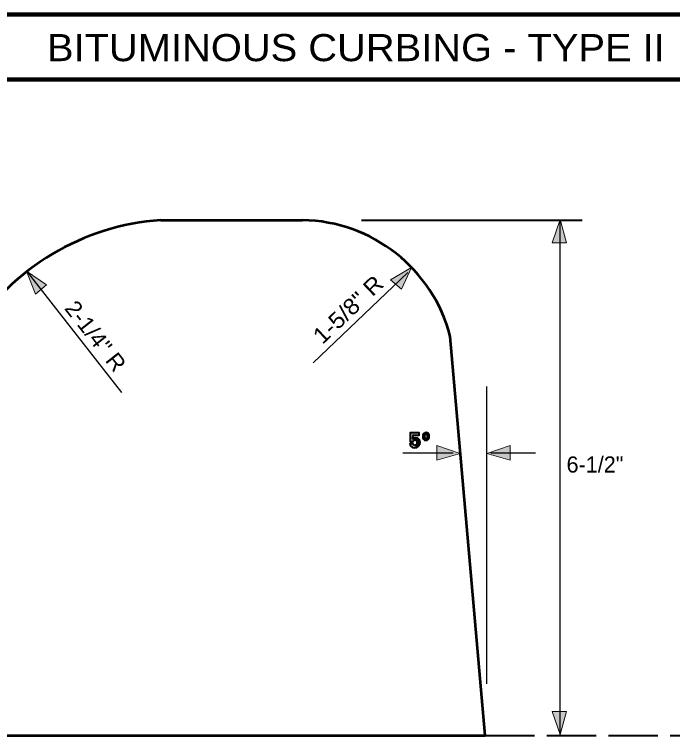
# Model space of a CAD drawing. Extents: x -9575 to -7980, y -62851 to -56618.
# Drawn here: x -9090 to -8521, y -62411 to -61789 of the extents above; entities that cross this region are included whole.
import ezdxf
from ezdxf.enums import TextEntityAlignment as Align

# ---------------------------------------------------------------- set-up
doc = ezdxf.new("R2010")
doc.units = 0
doc.header["$LTSCALE"] = 7.1
doc.linetypes.add('LONG_DASHED', pattern=[7.5, 6, -1.5])
doc.layers.add('1', color=7, linetype='Continuous', lineweight=13)
doc.layers.add('3', color=7, linetype='Continuous', lineweight=40)

msp = doc.modelspace()

# ---------------------------------------------------------------- hatches: boundary and pattern name
at = {"layer": '1'}
for points in [[(-8618.4, -61965.96), (-8625.3, -61985.96), (-8612.8, -61985.96)], [(-8746.68, -62007.2), (-8764.86, -62018), (-8755.32, -62026.08)], [(-9079.16, -62010.58), (-9071.52, -62030.32), (-9061.98, -62022.24)], [(-8704.8, -62167.92), (-8724.8, -62161.02), (-8724.8, -62173.52)], [(-8681.7, -62167.92), (-8661.7, -62161.02), (-8661.7, -62173.52)], [(-8618.4, -62410.64), (-8625.3, -62390.64), (-8612.8, -62390.64)]]:
    msp.add_hatch(color=256, dxfattribs=at).paths.add_polyline_path(points)
at = {"layer": '3'}
for points in [[(-8748.06, -62156.84), (-8748.08, -62157.5), (-8745.4, -62157.5), (-8745.06, -62156.84), (-8745.06, -62156.84), (-8745.06, -62156.84), (-8745.06, -62156.84), (-8744.52, -62156.38), (-8744.4, -62156.36), (-8743.86, -62156.2), (-8739.98, -62156.2), (-8740.38, -62155.52), (-8740.86, -62155.2), (-8745.58, -62155.2), (-8745.54, -62154.64), (-8745.54, -62154.6), (-8745.38, -62152.08), (-8740.18, -62152.08), (-8740.18, -62150.04), (-8747.8, -62150.04), (-8747.88, -62152.08), (-8747.98, -62154.6), (-8747.98, -62154.64), (-8748, -62155.2), (-8748.02, -62155.52), (-8748.04, -62156.2), (-8748.04, -62156.36), (-8748.04, -62156.38), (-8748.06, -62156.84), (-8748.06, -62156.84)], [(-8736.98, -62154.38), (-8736.98, -62154.52), (-8735.1, -62154.52), (-8735.14, -62154.38), (-8735.26, -62153.96), (-8735.28, -62153.88), (-8735.34, -62153.18), (-8735.34, -62153.16), (-8735.34, -62153.08), (-8735.32, -62153.02), (-8735.26, -62152.36), (-8735.24, -62152.24), (-8735.1, -62151.82), (-8735.06, -62151.66), (-8735.04, -62151.64), (-8735.04, -62151.64), (-8735.02, -62151.6), (-8734.7, -62151.26), (-8734.62, -62151.24), (-8734.26, -62151.14), (-8731.88, -62151.14), (-8732.14, -62150.68), (-8732.2, -62150.58), (-8733.12, -62150), (-8733.18, -62149.98), (-8734.26, -62149.82), (-8735.22, -62149.98), (-8735.42, -62150), (-8736.26, -62150.58), (-8736.38, -62150.68), (-8736.62, -62151.14), (-8736.66, -62151.24), (-8736.68, -62151.26), (-8736.86, -62151.6), (-8736.88, -62151.64), (-8736.9, -62151.66), (-8736.98, -62151.82), (-8737.02, -62152.24), (-8737.04, -62152.36), (-8737.12, -62153.02), (-8737.14, -62153.08), (-8737.14, -62153.16), (-8737.14, -62153.18), (-8737.06, -62153.88), (-8737.04, -62153.96)], [(-8733.92, -62155.06), (-8734.24, -62155.16), (-8731.94, -62155.16), (-8731.88, -62155.06), (-8731.86, -62155), (-8731.68, -62154.64), (-8731.66, -62154.56), (-8731.62, -62154.52), (-8731.56, -62154.38), (-8731.52, -62153.96), (-8731.5, -62153.88), (-8731.42, -62153.18), (-8731.42, -62153.16), (-8731.4, -62153.08), (-8731.4, -62153.02), (-8731.5, -62152.36), (-8731.52, -62152.24), (-8731.58, -62151.82), (-8731.6, -62151.66), (-8731.6, -62151.64), (-8731.62, -62151.6), (-8731.62, -62151.6), (-8731.82, -62151.26), (-8731.82, -62151.26), (-8731.84, -62151.24), (-8731.88, -62151.14), (-8734.26, -62151.14), (-8733.86, -62151.24), (-8733.84, -62151.26), (-8733.5, -62151.6), (-8733.5, -62151.64), (-8733.48, -62151.66), (-8733.42, -62151.82), (-8733.28, -62152.24), (-8733.26, -62152.36), (-8733.22, -62153.02), (-8733.2, -62153.08), (-8733.22, -62153.16), (-8733.22, -62153.18), (-8733.26, -62153.88), (-8733.28, -62153.96), (-8733.4, -62154.38), (-8733.44, -62154.52), (-8733.46, -62154.56), (-8733.5, -62154.64), (-8733.78, -62155)], [(-8744.7, -62154.64), (-8745.58, -62155.2), (-8740.86, -62155.2), (-8741.66, -62154.64), (-8741.82, -62154.6), (-8744.66, -62154.6)], [(-8743.22, -62154.32), (-8744.66, -62154.6), (-8741.82, -62154.6), (-8743.22, -62154.32)], [(-8743.36, -62160.76), (-8743.86, -62160.92), (-8740.22, -62160.92), (-8740.12, -62160.76), (-8740.1, -62160.74), (-8740.06, -62160.7), (-8739.78, -62160.26), (-8739.72, -62160.18), (-8739.72, -62160.14), (-8739.56, -62159.28), (-8739.4, -62158.42), (-8739.38, -62158.32), (-8739.5, -62157.6), (-8739.5, -62157.5), (-8739.62, -62156.84), (-8739.62, -62156.84), (-8739.62, -62156.84), (-8739.88, -62156.38), (-8739.9, -62156.36), (-8739.98, -62156.2), (-8743.86, -62156.2), (-8743.08, -62156.36), (-8743.06, -62156.38), (-8742.56, -62156.84), (-8742.54, -62156.84), (-8742.54, -62156.84), (-8742.24, -62157.5), (-8742.18, -62157.6), (-8742.1, -62158.32), (-8742.1, -62158.42), (-8742.18, -62159.28), (-8742.5, -62160.14), (-8742.54, -62160.18), (-8742.62, -62160.26), (-8743.1, -62160.7), (-8743.26, -62160.74)], [(-8736.5, -62155.48), (-8736.44, -62155.6), (-8732.22, -62155.6), (-8732.08, -62155.48), (-8731.94, -62155.16), (-8734.24, -62155.16), (-8734.72, -62155.06), (-8734.76, -62155), (-8735.08, -62154.64), (-8735.1, -62154.56), (-8735.1, -62154.52), (-8736.98, -62154.52), (-8736.94, -62154.56), (-8736.92, -62154.64), (-8736.74, -62155), (-8736.7, -62155.06), (-8736.66, -62155.16)], [(-8734.38, -62156.48), (-8734.18, -62156.5), (-8734.04, -62156.48), (-8733.88, -62156.44), (-8733.36, -62156.32), (-8732.96, -62156.24), (-8732.22, -62155.6), (-8736.44, -62155.6), (-8735.58, -62156.24), (-8735.46, -62156.32), (-8734.64, -62156.44)], [(-8745.94, -62162.66), (-8744.14, -62162.96), (-8742.34, -62162.66), (-8742.34, -62162.66), (-8742.3, -62162.66), (-8741.02, -62161.86), (-8740.72, -62161.68), (-8740.22, -62160.92), (-8743.86, -62160.92), (-8744.66, -62160.76), (-8744.68, -62160.74), (-8744.74, -62160.7), (-8745.2, -62160.26), (-8745.22, -62160.18), (-8745.22, -62160.14), (-8745.36, -62159.56), (-8748.1, -62159.56), (-8748.02, -62160.14), (-8748.02, -62160.18), (-8748.02, -62160.26), (-8747.94, -62160.7), (-8747.94, -62160.74), (-8747.92, -62160.76), (-8747.82, -62160.92), (-8747.34, -62161.68), (-8747.22, -62161.86), (-8745.94, -62162.66)]]:
    msp.add_hatch(color=256, dxfattribs=at).paths.add_polyline_path(points)

# ---------------------------------------------------------------- linework, layer by layer
at = {"layer": '1', "lineweight": 100}
for p, q in [((-8031.28, -61788.8), (-9523.5, -61788.8)), ((-8031.28, -61845.06), (-9523.5, -61845.06))]:
    msp.add_line(p, q, dxfattribs=at)
at = {"layer": '1'}
for points in [[(-8618.4, -61965.96), (-8625.3, -61985.96), (-8612.8, -61985.96)], [(-8746.68, -62007.2), (-8764.86, -62018), (-8755.32, -62026.08)], [(-9079.16, -62010.58), (-9071.52, -62030.32), (-9061.98, -62022.24)], [(-8704.8, -62167.92), (-8724.8, -62161.02), (-8724.8, -62173.52)], [(-8681.7, -62167.92), (-8661.7, -62161.02), (-8661.7, -62173.52)], [(-8618.4, -62410.64), (-8625.3, -62390.64), (-8612.8, -62390.64)]]:
    msp.add_lwpolyline(points, close=True, dxfattribs=at)
at = {"layer": '3', "lineweight": 53}
for p, q in [((-8963.38, -61966.4), (-8840.98, -61966.4)), ((-8683.18, -62411.44), (-8713.34, -62066.76)), ((-9285.14, -62411.44), (-8683.18, -62411.44))]:
    msp.add_line(p, q, dxfattribs=at)
at = {"layer": '3'}
msp.add_line((-8789.98, -61966.4), (-8599.34, -61966.4), dxfattribs=at)
at = {"layer": '3', "lineweight": 25}
for p, q in [((-8618.38, -62411.44), (-8618.38, -61966.4)), ((-9078.88, -62010.8), (-8997.14, -62115.2)), ((-8749.9, -62011.64), (-8831.82, -62089.7)), ((-8681.68, -62366.9), (-8681.68, -62110.1)), ((-8754.14, -62167.4), (-8710.74, -62167.4)), ((-8678.26, -62167.4), (-8639.68, -62167.4))]:
    msp.add_line(p, q, dxfattribs=at)
at = {"layer": '3', "linetype": 'LONG_DASHED'}
msp.add_line((-8683.18, -62411.44), (-8470.48, -62411.44), dxfattribs=at)
at = {"layer": '3'}
for points in [[(-8748.06, -62156.84), (-8748.08, -62157.5), (-8745.4, -62157.5), (-8745.06, -62156.84), (-8745.06, -62156.84), (-8745.06, -62156.84), (-8745.06, -62156.84), (-8744.52, -62156.38), (-8744.4, -62156.36), (-8743.86, -62156.2), (-8739.98, -62156.2), (-8740.38, -62155.52), (-8740.86, -62155.2), (-8745.58, -62155.2), (-8745.54, -62154.64), (-8745.54, -62154.6), (-8745.38, -62152.08), (-8740.18, -62152.08), (-8740.18, -62150.04), (-8747.8, -62150.04), (-8747.88, -62152.08), (-8747.98, -62154.6), (-8747.98, -62154.64), (-8748, -62155.2), (-8748.02, -62155.52), (-8748.04, -62156.2), (-8748.04, -62156.36), (-8748.04, -62156.38), (-8748.06, -62156.84), (-8748.06, -62156.84)], [(-8736.98, -62154.38), (-8736.98, -62154.52), (-8735.1, -62154.52), (-8735.14, -62154.38), (-8735.26, -62153.96), (-8735.28, -62153.88), (-8735.34, -62153.18), (-8735.34, -62153.16), (-8735.34, -62153.08), (-8735.32, -62153.02), (-8735.26, -62152.36), (-8735.24, -62152.24), (-8735.1, -62151.82), (-8735.06, -62151.66), (-8735.04, -62151.64), (-8735.04, -62151.64), (-8735.02, -62151.6), (-8734.7, -62151.26), (-8734.62, -62151.24), (-8734.26, -62151.14), (-8731.88, -62151.14), (-8732.14, -62150.68), (-8732.2, -62150.58), (-8733.12, -62150), (-8733.18, -62149.98), (-8734.26, -62149.82), (-8735.22, -62149.98), (-8735.42, -62150), (-8736.26, -62150.58), (-8736.38, -62150.68), (-8736.62, -62151.14), (-8736.66, -62151.24), (-8736.68, -62151.26), (-8736.86, -62151.6), (-8736.88, -62151.64), (-8736.9, -62151.66), (-8736.98, -62151.82), (-8737.02, -62152.24), (-8737.04, -62152.36), (-8737.12, -62153.02), (-8737.14, -62153.08), (-8737.14, -62153.16), (-8737.14, -62153.18), (-8737.06, -62153.88), (-8737.04, -62153.96)], [(-8733.92, -62155.06), (-8734.24, -62155.16), (-8731.94, -62155.16), (-8731.88, -62155.06), (-8731.86, -62155), (-8731.68, -62154.64), (-8731.66, -62154.56), (-8731.62, -62154.52), (-8731.56, -62154.38), (-8731.52, -62153.96), (-8731.5, -62153.88), (-8731.42, -62153.18), (-8731.42, -62153.16), (-8731.4, -62153.08), (-8731.4, -62153.02), (-8731.5, -62152.36), (-8731.52, -62152.24), (-8731.58, -62151.82), (-8731.6, -62151.66), (-8731.6, -62151.64), (-8731.62, -62151.6), (-8731.62, -62151.6), (-8731.82, -62151.26), (-8731.82, -62151.26), (-8731.84, -62151.24), (-8731.88, -62151.14), (-8734.26, -62151.14), (-8733.86, -62151.24), (-8733.84, -62151.26), (-8733.5, -62151.6), (-8733.5, -62151.64), (-8733.48, -62151.66), (-8733.42, -62151.82), (-8733.28, -62152.24), (-8733.26, -62152.36), (-8733.22, -62153.02), (-8733.2, -62153.08), (-8733.22, -62153.16), (-8733.22, -62153.18), (-8733.26, -62153.88), (-8733.28, -62153.96), (-8733.4, -62154.38), (-8733.44, -62154.52), (-8733.46, -62154.56), (-8733.5, -62154.64), (-8733.78, -62155)], [(-8744.7, -62154.64), (-8745.58, -62155.2), (-8740.86, -62155.2), (-8741.66, -62154.64), (-8741.82, -62154.6), (-8744.66, -62154.6)], [(-8743.22, -62154.32), (-8744.66, -62154.6), (-8741.82, -62154.6), (-8743.22, -62154.32)], [(-8743.36, -62160.76), (-8743.86, -62160.92), (-8740.22, -62160.92), (-8740.12, -62160.76), (-8740.1, -62160.74), (-8740.06, -62160.7), (-8739.78, -62160.26), (-8739.72, -62160.18), (-8739.72, -62160.14), (-8739.56, -62159.28), (-8739.4, -62158.42), (-8739.38, -62158.32), (-8739.5, -62157.6), (-8739.5, -62157.5), (-8739.62, -62156.84), (-8739.62, -62156.84), (-8739.62, -62156.84), (-8739.88, -62156.38), (-8739.9, -62156.36), (-8739.98, -62156.2), (-8743.86, -62156.2), (-8743.08, -62156.36), (-8743.06, -62156.38), (-8742.56, -62156.84), (-8742.54, -62156.84), (-8742.54, -62156.84), (-8742.24, -62157.5), (-8742.18, -62157.6), (-8742.1, -62158.32), (-8742.1, -62158.42), (-8742.18, -62159.28), (-8742.5, -62160.14), (-8742.54, -62160.18), (-8742.62, -62160.26), (-8743.1, -62160.7), (-8743.26, -62160.74)], [(-8736.5, -62155.48), (-8736.44, -62155.6), (-8732.22, -62155.6), (-8732.08, -62155.48), (-8731.94, -62155.16), (-8734.24, -62155.16), (-8734.72, -62155.06), (-8734.76, -62155), (-8735.08, -62154.64), (-8735.1, -62154.56), (-8735.1, -62154.52), (-8736.98, -62154.52), (-8736.94, -62154.56), (-8736.92, -62154.64), (-8736.74, -62155), (-8736.7, -62155.06), (-8736.66, -62155.16)], [(-8734.38, -62156.48), (-8734.18, -62156.5), (-8734.04, -62156.48), (-8733.88, -62156.44), (-8733.36, -62156.32), (-8732.96, -62156.24), (-8732.22, -62155.6), (-8736.44, -62155.6), (-8735.58, -62156.24), (-8735.46, -62156.32), (-8734.64, -62156.44)], [(-8745.94, -62162.66), (-8744.14, -62162.96), (-8742.34, -62162.66), (-8742.34, -62162.66), (-8742.3, -62162.66), (-8741.02, -62161.86), (-8740.72, -62161.68), (-8740.22, -62160.92), (-8743.86, -62160.92), (-8744.66, -62160.76), (-8744.68, -62160.74), (-8744.74, -62160.7), (-8745.2, -62160.26), (-8745.22, -62160.18), (-8745.22, -62160.14), (-8745.36, -62159.56), (-8748.1, -62159.56), (-8748.02, -62160.14), (-8748.02, -62160.18), (-8748.02, -62160.26), (-8747.94, -62160.7), (-8747.94, -62160.74), (-8747.92, -62160.76), (-8747.82, -62160.92), (-8747.34, -62161.68), (-8747.22, -62161.86), (-8745.94, -62162.66)]]:
    msp.add_lwpolyline(points, close=True, dxfattribs=at)
at = {"layer": '3', "lineweight": 53}
for centre, radius, start, end in [((-8948.76, -62176.88), 210.98, 93.97195, 147.8167), ((-8843.1, -62100.47), 134.08, 14.56284, 89.09298)]:
    msp.add_arc(centre, radius, start, end, dxfattribs=at)

# ---------------------------------------------------------------- texts
at = {"layer": '3', "width": 1.1}
msp.add_text('BITUMINOUS CURBING - TYPE II', height=23.4, dxfattribs=at).set_placement((-8794.8, -61829.16), align=Align.CENTER)
at = {"layer": '3'}
for s, rotation, width, p in [('1-5/8" R', 43.615, 1.1, (-8823.74, -62074.32)), ('2-1/4" R', 308.063, 1.05, (-9047.08, -62042.8))]:
    msp.add_text(s, height=13.95, rotation=rotation, dxfattribs=dict(at, width=width)).set_placement(p)
msp.add_text(' 6-1/2"', height=13.95, dxfattribs=at).set_placement((-8618.08, -62184.36))

doc.saveas('drawing.dxf')
